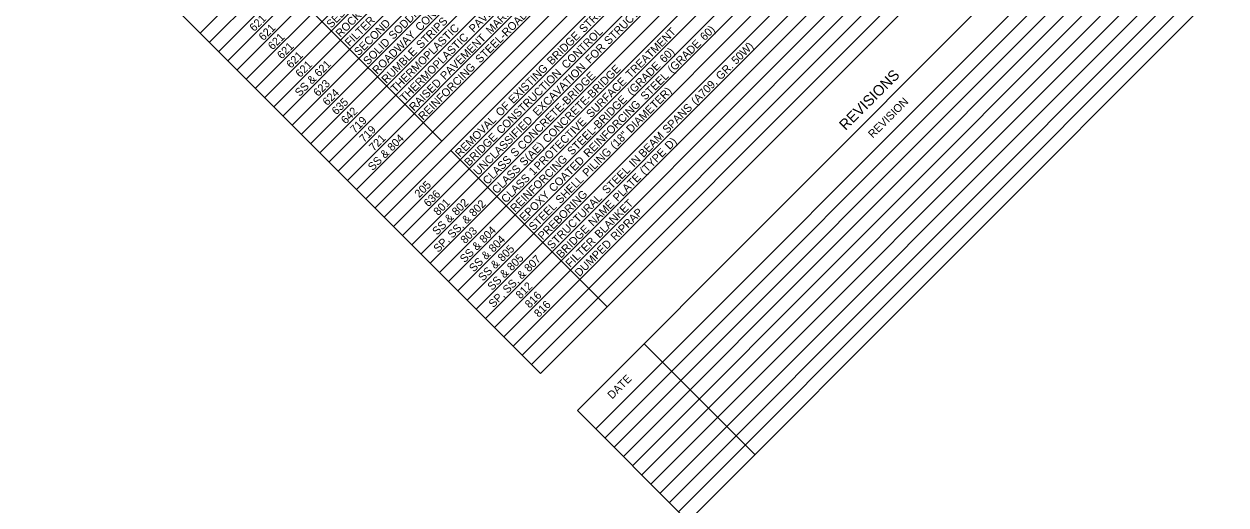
# Model space of a CAD drawing. Extents: x 1675667 to 1681231, y 227227 to 232694.
# Drawn here: x 1679879 to 1680780, y 231182 to 231542 of the extents above; entities that cross this region are included whole.
import ezdxf

# ---------------------------------------------------------------- set-up
doc = ezdxf.new("R2010")
doc.units = 0
doc.layers.add('Default', color=7, linetype='Continuous')

msp = doc.modelspace()

# ---------------------------------------------------------------- linework, layer by layer
at = {"layer": 'Default'}
for p, q in [((1680011.14, 231535.11), (1680484.38, 232008.46)), ((1680018.04, 231528.22), (1680491.27, 232001.57)), ((1680024.93, 231521.32), (1680498.17, 231994.67)), ((1680031.83, 231514.43), (1680505.06, 231987.78)), ((1680038.72, 231507.54), (1680511.96, 231980.89)), ((1680045.62, 231500.64), (1680518.85, 231973.99)), ((1680052.51, 231493.75), (1680525.75, 231967.1)), ((1680059.41, 231486.86), (1680532.65, 231960.21)), ((1680066.31, 231479.96), (1680539.54, 231953.31)), ((1680073.2, 231473.07), (1680546.44, 231946.42)), ((1680080.1, 231466.18), (1680553.33, 231939.53)), ((1680086.99, 231459.28), (1680560.23, 231932.63)), ((1680093.89, 231452.39), (1680567.12, 231925.74)), ((1680100.78, 231445.5), (1680574.02, 231918.85)), ((1680107.68, 231438.6), (1680580.91, 231911.95)), ((1680114.57, 231431.71), (1680587.81, 231905.06)), ((1680192.13, 231454.12), (1679751.19, 231894.96)), ((1680121.47, 231424.82), (1680594.7, 231898.17)), ((1680128.36, 231417.92), (1680601.6, 231891.27)), ((1680135.26, 231411.03), (1680608.49, 231884.38)), ((1680192.13, 231454.12), (1679771.87, 231874.28)), ((1680142.15, 231404.14), (1680615.39, 231877.49)), ((1680149.05, 231397.24), (1680622.28, 231870.59)), ((1680155.94, 231390.35), (1680629.18, 231863.7)), ((1680162.84, 231383.45), (1680636.07, 231856.81)), ((1680169.73, 231376.56), (1680642.97, 231849.91)), ((1680266.26, 231280.05), (1679701.21, 231844.97)), ((1680266.26, 231280.05), (1679701.21, 231844.97)), ((1680176.63, 231369.67), (1680649.86, 231843.02)), ((1680183.52, 231362.77), (1680656.76, 231836.13)), ((1680190.42, 231355.88), (1680663.65, 231829.23)), ((1680197.31, 231348.99), (1680670.55, 231822.34)), ((1680204.21, 231342.09), (1680677.44, 231815.45)), ((1680211.1, 231335.2), (1680684.34, 231808.55)), ((1680218, 231328.31), (1680691.23, 231801.66)), ((1680224.89, 231321.41), (1680698.13, 231794.77)), ((1680231.79, 231314.52), (1680705.02, 231787.87)), ((1680238.68, 231307.63), (1680711.92, 231780.98)), ((1680245.58, 231300.73), (1680718.81, 231774.08)), ((1680252.47, 231293.84), (1680725.71, 231767.19)), ((1680259.37, 231286.95), (1680732.6, 231760.3)), ((1680266.26, 231280.05), (1680739.5, 231753.4)), ((1680293.84, 231252.48), (1680767.08, 231725.83)), ((1680307.63, 231238.69), (1680780.87, 231712.04)), ((1680314.53, 231231.8), (1680787.77, 231705.15)), ((1680321.43, 231224.91), (1680794.66, 231698.26)), ((1680328.32, 231218.01), (1680801.56, 231691.36)), ((1680335.22, 231211.12), (1680808.45, 231684.47)), ((1680342.11, 231204.23), (1680815.35, 231677.58)), ((1680349.01, 231197.33), (1680822.24, 231670.68)), ((1680355.9, 231190.44), (1680829.14, 231663.79)), ((1680362.8, 231183.54), (1680836.03, 231656.9)), ((1680369.69, 231176.65), (1680842.93, 231650)), ((1680376.93, 231169.41), (1680850.17, 231642.76)), ((1680316.24, 231330.04), (1680199.02, 231447.23)), ((1680316.24, 231330.04), (1680199.02, 231447.23)), ((1680293.84, 231252.48), (1680343.82, 231302.47)), ((1680426.91, 231219.4), (1680343.82, 231302.47)), ((1680376.93, 231169.41), (1680293.84, 231252.48)), ((1680376.93, 231169.41), (1680293.84, 231252.48))]:
    msp.add_line(p, q, dxfattribs=at)

# ---------------------------------------------------------------- texts
for s, height, p in [(' CONSTRUCTION', 6, (1680174.29, 231534.51)), (' STRUCTURES-BRIDGE', 6, (1680315.83, 231524.39)), ('SEDIMENT', 6, (1680109.23, 231538.38)), (' PAVEMENT', 6, (1680214.54, 231533.4)), (' STRUCTURE', 6, (1680297.14, 231533.28)), (' SODDING', 6, (1680154.28, 231528.28)), (' STEEL-ROADWAY', 6, (1680219.3, 231510.58)), (' MARKERS', 6, (1680227.18, 231532.25)), ('621', 6, (1680051.57, 231535.88)), ('ROCK', 6, (1680116.12, 231531.49)), ('621', 6, (1680058.47, 231528.98)), ('FILTER', 6, (1680123.02, 231524.6)), ('SECOND', 6, (1680129.91, 231517.7)), ('THERMOPLASTIC', 6, (1680157.49, 231490.13)), (' STRIPS', 6, (1680174.98, 231521.42)), (' TREATMENT', 6, (1680332.08, 231499.27)), (' 60)', 6, (1680387.8, 231527.43)), ('621', 6, (1680065.36, 231522.09)), ('SOLID', 6, (1680136.81, 231510.81)), ('ROADWAY', 6, (1680143.7, 231503.92)), ('THERMOPLASTIC', 6, (1680164.39, 231483.24)), (' PAVEMENT', 6, (1680193.04, 231498.1)), (' BRIDGE', 6, (1680273.08, 231509.22)), (' CONTROL', 6, (1680283.98, 231506.32)), (' (GRADE', 6, (1680363.42, 231503.05)), ('621', 6, (1680072.26, 231515.19)), ('RUMBLE', 6, (1680150.6, 231497.02)), (' FOR', 6, (1680301.75, 231510.31)), (' 60)', 6, (1680357.44, 231510.85)), (' 50W)', 6, (1680411.33, 231509.59)), ('621', 6, (1680079.15, 231508.3)), ('621', 6, (1680086.05, 231501.41)), (' 621', 6, (1680098.65, 231500.22)), ('REINFORCING', 6, (1680178.18, 231469.45)), (' EXCAVATION', 6, (1680262.38, 231470.93)), (' (GRADE', 6, (1680333.06, 231486.47)), (' CONSTRUCTION', 6, (1680235.07, 231457.4)), (' EXISTING', 6, (1680244.14, 231480.27)), (' CONCRETE-BRIDGE', 6, (1680250.86, 231445.62)), (' CONCRETE-BRIDGE', 6, (1680269.71, 231450.68)), (' STEEL', 6, (1680343.21, 231482.83)), (' GR.', 6, (1680399.66, 231497.92)), ('REVISIONS', 8, (1680494.9, 231461.72)), ('SS', 6, (1680085.59, 231487.16)), (' &', 6, (1680093.19, 231494.76)), ('623', 6, (1680099.43, 231487.21)), ('RAISED', 6, (1680171.28, 231476.34)), (' SURFACE', 6, (1680302.42, 231469.61)), (' DIAMETER)', 6, (1680332.45, 231458.27)), (' (A709,', 6, (1680381.09, 231479.34)), ('624', 6, (1680106.33, 231480.33)), ('635', 6, (1680113.2, 231473.41)), (' STEEL-BRIDGE', 6, (1680288.25, 231441.65)), ('REVISION', 6, (1680515.39, 231456.04)), ('642', 6, (1680120.14, 231466.55)), (' OF', 6, (1680234.54, 231470.66)), (' REINFORCING', 6, (1680300.44, 231440.05)), (' SPANS', 6, (1680359.65, 231457.91)), ('719', 6, (1680127, 231459.63)), ('REMOVAL', 6, (1680205.76, 231441.88)), ('UNCLASSIFIED', 6, (1680219.55, 231428.09)), (' PROTECTIVE', 6, (1680263.22, 231430.39)), ('719', 6, (1680133.9, 231452.74)), ('721', 6, (1680141.21, 231446.26)), (' 804', 6, (1680153.41, 231444.68)), ('BRIDGE', 6, (1680212.66, 231434.98)), (' (18"', 6, (1680320.41, 231446.23)), (' BEAM', 6, (1680341.65, 231439.9)), (' S', 6, (1680245.57, 231440.33)), (' S(AE)', 6, (1680252.47, 231433.44)), (' (TYPE', 6, (1680342.58, 231427.04)), (' D)', 6, (1680361.37, 231445.83)), ('SS', 6, (1680140.35, 231431.61)), (' &', 6, (1680147.95, 231439.21)), ('CLASS', 6, (1680226.45, 231421.2)), ('REINFORCING', 6, (1680247.13, 231400.52)), (' COATED', 6, (1680274.41, 231414.01)), (' PILING', 6, (1680299.7, 231425.52)), (' IN', 6, (1680334.57, 231432.81)), ('CLASS', 6, (1680233.34, 231414.3)), (' 1', 6, (1680259.36, 231426.54)), (' STEEL', 6, (1680314.35, 231412.59)), ('205', 6, (1680175.26, 231411.37)), ('CLASS', 6, (1680240.24, 231407.41)), (' SHELL', 6, (1680279.49, 231405.3)), (' PLATE', 6, (1680322.47, 231406.92)), ('636', 6, (1680182.17, 231404.49)), ('EPOXY', 6, (1680254.03, 231393.62)), ('PREBORING', 6, (1680267.82, 231379.84)), ('STRUCTURAL', 6, (1680274.71, 231372.94)), ('801', 6, (1680189.48, 231398.01)), (' 802', 6, (1680201.69, 231396.43)), (' 802', 6, (1680214.64, 231395.59)), ('STEEL', 6, (1680260.92, 231386.73)), (' NAME', 6, (1680304.02, 231388.46)), (' BLANKET', 6, (1680308.84, 231379.5)), (' &', 6, (1680196.23, 231390.97)), (' &', 6, (1680209.17, 231390.13)), (' RIPRAP', 6, (1680320.77, 231377.64)), ('SS', 6, (1680188.63, 231383.37)), (' SS,', 6, (1680198.5, 231379.45)), ('803', 6, (1680209.75, 231376.92)), (' 804', 6, (1680222.36, 231375.74)), ('BRIDGE', 6, (1680281.61, 231366.05)), ('SP,', 6, (1680189.47, 231370.42)), (' &', 6, (1680216.9, 231370.28)), (' 804', 6, (1680229.26, 231368.85)), ('FILTER', 6, (1680288.5, 231359.15)), ('DUMPED', 6, (1680295.4, 231352.26)), ('SS', 6, (1680209.3, 231362.68)), (' &', 6, (1680223.79, 231363.38)), (' 805', 6, (1680236.13, 231361.93)), (' 805', 6, (1680243.02, 231355.04)), (' 807', 6, (1680255.99, 231354.21)), ('SS', 6, (1680216.2, 231355.78)), ('SS', 6, (1680223.06, 231348.86)), (' &', 6, (1680230.66, 231356.46)), ('SS', 6, (1680229.96, 231341.97)), (' &', 6, (1680237.56, 231349.57)), (' SS,', 6, (1680239.85, 231338.07)), (' &', 6, (1680250.52, 231348.74)), ('812', 6, (1680251.14, 231335.58)), ('816', 6, (1680258.02, 231328.66)), ('SP,', 6, (1680230.82, 231329.04)), ('816', 6, (1680264.91, 231321.77)), ('DATE', 6, (1680319.93, 231260.54))]:
    msp.add_text(s, height=height, rotation=45.00703, dxfattribs=at).set_placement(p)

doc.saveas('drawing.dxf')
